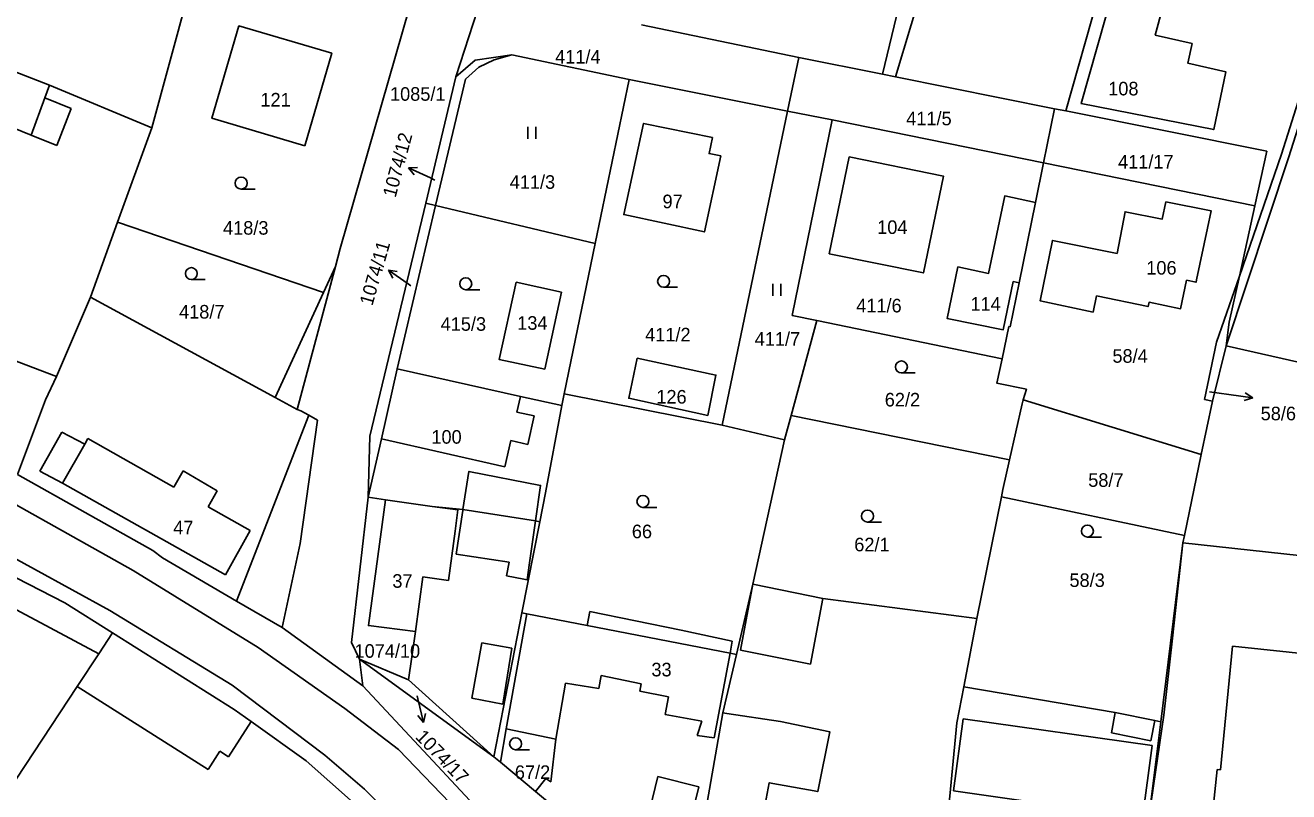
# Model space of a CAD drawing. Extents: x -746176 to -739709, y -1127410 to -1124482.
# Drawn here: x -742391.9 to -742233.7, y -1126006.4 to -1125910.5 of the extents above; entities that cross this region are included whole.
import ezdxf

# ---------------------------------------------------------------- set-up
doc = ezdxf.new("R2010")
doc.units = 0
for name, color, linetype in [('Hranice parcel', 7, 'Continuous'), ('Parcelní čísla', 7, 'Continuous'), ('Pop  PČ popisy', 7, 'Continuous'), ('Vnitřní kresba', 7, 'Continuous'), ('Značky kultur', 7, 'Continuous')]:
    doc.layers.add(name, color=color, linetype=linetype)

msp = doc.modelspace()

# ---------------------------------------------------------------- linework, layer by layer
at = {"layer": 'Hranice parcel'}
for p, q in [((-742261.6, -1125921.22), (-742251.35, -1125885.17)), ((-742284.56, -1125916.62), (-742279.49, -1125895.76)), ((-742369.56, -1125899.45), (-742376.04, -1125923.32)), ((-742337.98, -1125916.93), (-742332.93, -1125901.45)), ((-742314.74, -1125910.42), (-742295.02, -1125914.52)), ((-742316.28, -1125917.27), (-742330.95, -1125914.18)), ((-742296.43, -1125921.26), (-742295.02, -1125914.52)), ((-742295.02, -1125914.52), (-742284.56, -1125916.62)), ((-742341.73, -1125932.77), (-742337.98, -1125916.93)), ((-742316.28, -1125917.27), (-742320.52, -1125937.81)), ((-742296.43, -1125921.26), (-742316.28, -1125917.27)), ((-742282.91, -1125916.95), (-742284.56, -1125916.62)), ((-742282.91, -1125916.95), (-742263.01, -1125920.94)), ((-742264.39, -1125927.72), (-742263.01, -1125920.94)), ((-742263.01, -1125920.94), (-742261.6, -1125921.22)), ((-742304.63, -1125960.54), (-742296.43, -1125921.26)), ((-742296.43, -1125921.26), (-742290.84, -1125922.32)), ((-742290.84, -1125922.32), (-742264.39, -1125927.72)), ((-742380.33, -1125935.12), (-742376.04, -1125923.32)), ((-742264.39, -1125927.72), (-742265.4, -1125932.68)), ((-742237.93, -1125933.1), (-742264.39, -1125927.72)), ((-742340.51, -1125933.06), (-742345.34, -1125953.5)), ((-742340.51, -1125933.06), (-742341.73, -1125932.77)), ((-742340.51, -1125933.06), (-742320.52, -1125937.81)), ((-742267.46, -1125942.71), (-742265.4, -1125932.68)), ((-742239.87, -1125941.89), (-742237.93, -1125933.1)), ((-742380.33, -1125935.12), (-742383.73, -1125944.51)), ((-742354.55, -1125943.93), (-742380.33, -1125935.12)), ((-742320.52, -1125937.81), (-742324.4, -1125956.6)), ((-742353.05, -1125940.67), (-742354.55, -1125943.93)), ((-742383.73, -1125944.51), (-742387.99, -1125954.45)), ((-742360.59, -1125957.08), (-742383.73, -1125944.51)), ((-742360.59, -1125957.08), (-742354.55, -1125943.93)), ((-742292.77, -1125947.44), (-742295.99, -1125959.35)), ((-742269.58, -1125952.24), (-742292.77, -1125947.44)), ((-742241.51, -1125950.63), (-742243.24, -1125957.53)), ((-742215.07, -1125956.62), (-742241.51, -1125950.63)), ((-742324.4, -1125956.6), (-742324.69, -1125958.1)), ((-742304.63, -1125960.54), (-742324.4, -1125956.6)), ((-742266.93, -1125957.38), (-742244.64, -1125964.23)), ((-742243.24, -1125957.53), (-742244.64, -1125964.23)), ((-742243.24, -1125957.53), (-742244.22, -1125957.34)), ((-742296.81, -1125962.38), (-742304.63, -1125960.54)), ((-742295.99, -1125959.35), (-742296.81, -1125962.38)), ((-742268.65, -1125964.88), (-742295.99, -1125959.35)), ((-742296.81, -1125962.38), (-742300.78, -1125980.44)), ((-742244.64, -1125964.23), (-742246.75, -1125974.33)), ((-742348.95, -1125969.57), (-742346.78, -1125969.9)), ((-742269.67, -1125969.51), (-742272.76, -1125984.75)), ((-742246.75, -1125974.33), (-742269.67, -1125969.51)), ((-742329.7, -1125984.02), (-742327.47, -1125972.62)), ((-742246.75, -1125974.33), (-742246.94, -1125975.25)), ((-742246.94, -1125975.25), (-742249.72, -1125997.65)), ((-742246.94, -1125975.25), (-742222.55, -1125977.95)), ((-742300.78, -1125980.44), (-742302.83, -1125989.25)), ((-742329.7, -1125984.02), (-742333.21, -1126002.03)), ((-742274.38, -1125993.3), (-742272.76, -1125984.75)), ((-742380.97, -1125986.53), (-742382.69, -1125989.14)), ((-742350.03, -1125989.81), (-742343.92, -1125992.41)), ((-742333.21, -1126002.03), (-742350.03, -1125989.81)), ((-742350.03, -1125989.81), (-742349.63, -1125993.16)), ((-742343.92, -1125992.41), (-742333.21, -1126002.03)), ((-742275.24, -1125997.79), (-742274.38, -1125993.3)), ((-742276.95, -1126015.87), (-742275.24, -1125997.79)), ((-742249.72, -1125997.65), (-742254.82, -1126038.74)), ((-742332.39, -1126002.71), (-742333.21, -1126002.03)), ((-742327.99, -1126006.38), (-742332.39, -1126002.71))]:
    msp.add_line(p, q, dxfattribs=at)
for points in [[(-742241.51, -1125950.63), (-742233.66, -1125926.96), (-742223.23, -1125894.07), (-742218.91, -1125880.44), (-742217.69, -1125875.07), (-742216.33, -1125869.06)], [(-742239.87, -1125941.89), (-742234.61, -1125926.63), (-742224.19, -1125893.77)], [(-742279.49, -1125895.76), (-742277.04, -1125897.38), (-742282.91, -1125916.95)], [(-742252.47, -1125894.85), (-742259.69, -1125920.29), (-742243.08, -1125923.55), (-742241.58, -1125916.3), (-742246.33, -1125915.23), (-742245.79, -1125912.79), (-742250.41, -1125911.75), (-742246.32, -1125896.62), (-742252.47, -1125894.85)], [(-742343.77, -1125908.28), (-742352.46, -1125938.44), (-742353.05, -1125940.67)], [(-742356.87, -1125925.57), (-742368.52, -1125922.14), (-742365.15, -1125910.57), (-742353.51, -1125913.99), (-742356.87, -1125925.57)], [(-742376.04, -1125923.32), (-742388.87, -1125917.99), (-742404.91, -1125911.78)], [(-742330.95, -1125914.18), (-742333.17, -1125914.81), (-742335.12, -1125915.74), (-742336.77, -1125917.22), (-742340.51, -1125933.06)], [(-742337.98, -1125916.93), (-742335.56, -1125914.84), (-742330.95, -1125914.18)], [(-742261.6, -1125921.22), (-742236.44, -1125926.26), (-742237.93, -1125933.1)], [(-742305.85, -1125924.52), (-742314.47, -1125922.77), (-742316.95, -1125934.19), (-742306.85, -1125936.36), (-742304.8, -1125926.85), (-742306.27, -1125926.55), (-742305.85, -1125924.52)], [(-742290.84, -1125922.32), (-742295.85, -1125946.81), (-742292.77, -1125947.44)], [(-742288.73, -1125926.94), (-742291.23, -1125939.08), (-742279.43, -1125941.49), (-742276.92, -1125929.36), (-742288.73, -1125926.94)], [(-742265.4, -1125932.68), (-742269.24, -1125931.85), (-742271.28, -1125941.54), (-742275.1, -1125940.73), (-742276.46, -1125947.18), (-742269.43, -1125948.6), (-742268.18, -1125942.58), (-742267.46, -1125942.71)], [(-742348.95, -1125969.57), (-742348.77, -1125961.93), (-742341.73, -1125932.77)], [(-742249.09, -1125932.57), (-742249.52, -1125934.75), (-742254.17, -1125933.84), (-742255.18, -1125939.05), (-742263.28, -1125937.42), (-742264.8, -1125945), (-742258.18, -1125946.38), (-742257.75, -1125944.36), (-742251.29, -1125945.7), (-742251.18, -1125945.16), (-742247.23, -1125945.98), (-742246.48, -1125942.4), (-742245.29, -1125942.65), (-742245.23, -1125942.35), (-742243.85, -1125935.89), (-742243.41, -1125933.71), (-742249.09, -1125932.57)], [(-742324.73, -1125943.91), (-742326.85, -1125953.53), (-742332.56, -1125952.31), (-742330.42, -1125942.66), (-742324.73, -1125943.91)], [(-742267.46, -1125942.71), (-742268.58, -1125948.23), (-742268.73, -1125948.2), (-742269.58, -1125952.24)], [(-742244.22, -1125957.34), (-742242.72, -1125950.14), (-742239.87, -1125941.89)], [(-742241.51, -1125950.63), (-742241.14, -1125947.64), (-742239.87, -1125941.89)], [(-742417.31, -1125943.6), (-742412.38, -1125945.19), (-742387.99, -1125954.45)], [(-742315.28, -1125952.17), (-742305.42, -1125954.28), (-742306.43, -1125959.32), (-742316.33, -1125957.18), (-742315.28, -1125952.17)], [(-742269.58, -1125952.24), (-742270.22, -1125955.3), (-742266.54, -1125956.05), (-742266.93, -1125957.38)], [(-742444.75, -1125953.11), (-742386.93, -1125982.77), (-742380.97, -1125986.53)], [(-742387.99, -1125954.45), (-742389.36, -1125957.36), (-742392.86, -1125966.72)], [(-742345.34, -1125953.5), (-742347.31, -1125962.26), (-742348.95, -1125969.57)], [(-742324.69, -1125958.1), (-742329.9, -1125956.94), (-742345.34, -1125953.5)], [(-742382.69, -1125989.14), (-742398.6, -1125980.67), (-742445.94, -1125955.65)], [(-742357.41, -1125958.73), (-742357.86, -1125958.57), (-742360.59, -1125957.08)], [(-742268.65, -1125964.88), (-742267.07, -1125957.87), (-742266.93, -1125957.38)], [(-742365.43, -1125982.55), (-742356.37, -1125959.31), (-742357.41, -1125958.73)], [(-742327.47, -1125972.62), (-742326.77, -1125969.01), (-742324.69, -1125958.1)], [(-742269.67, -1125969.51), (-742269.48, -1125968.58), (-742268.65, -1125964.88)], [(-742392.86, -1125966.72), (-742375.94, -1125976.23), (-742374.7, -1125977.14), (-742365.43, -1125982.55)], [(-742327.47, -1125972.62), (-742328.01, -1125972.53), (-742327.37, -1125968.09), (-742336.35, -1125966.33), (-742337.09, -1125971.11), (-742340.95, -1125970.71), (-742346.78, -1125969.9)], [(-742350.03, -1125989.81), (-742351.04, -1125987.76), (-742348.95, -1125969.57)], [(-742346.78, -1125969.9), (-742348.93, -1125985.62), (-742343.03, -1125986.37), (-742343.92, -1125992.41)], [(-742272.76, -1125984.75), (-742292.04, -1125982.23), (-742300.78, -1125980.44)], [(-742365.43, -1125982.55), (-742359.74, -1125985.87), (-742349.63, -1125993.16)], [(-742302.83, -1125989.25), (-742303.65, -1125989.09), (-742321.55, -1125985.61), (-742329.11, -1125984.14), (-742329.7, -1125984.02)], [(-742380.97, -1125986.53), (-742365.73, -1125996.13), (-742363.63, -1125997.63), (-742356.74, -1126002.55), (-742344.5, -1126013.38)], [(-742382.69, -1125989.14), (-742385.4, -1125993.25), (-742394.08, -1126006.45)], [(-742302.83, -1125989.25), (-742304.53, -1125996.56), (-742309.51, -1126024.97)], [(-742349.63, -1125993.16), (-742329.2, -1126015.02), (-742324.67, -1126035.23)], [(-742249.72, -1125997.65), (-742250.44, -1125997.51), (-742255.43, -1125996.5), (-742274.38, -1125993.3)], [(-742332.39, -1126002.71), (-742331.66, -1125998.55), (-742325.47, -1125999.83), (-742326.09, -1126005.17), (-742326.73, -1126004.75), (-742327.99, -1126006.38)], [(-742309.51, -1126024.97), (-742309.85, -1126024.64), (-742311.67, -1126022.6), (-742317.81, -1126015.69), (-742320.62, -1126012.53), (-742327.99, -1126006.38)]]:
    msp.add_lwpolyline(points, dxfattribs=at)
at = {"layer": 'Pop  PČ popisy'}
for p, q in [((-742343.89, -1125928.332), (-742342.771, -1125928.301)), ((-742341.17, -1125929.6), (-742343.89, -1125928.332)), ((-742343.89, -1125928.332), (-742343.194, -1125929.209)), ((-742340.63, -1125929.86), (-742341.17, -1125929.6)), ((-742343.96, -1125942.86), (-742346.418, -1125941.139)), ((-742346.418, -1125941.139), (-742345.311, -1125941.303)), ((-742346.418, -1125941.139), (-742345.885, -1125942.123)), ((-742343.6, -1125943.11), (-742343.96, -1125942.86)), ((-742243.59, -1125956.38), (-742241.17, -1125956.7)), ((-742241.17, -1125956.7), (-742238.198, -1125957.118)), ((-742238.198, -1125957.118), (-742239.26, -1125957.474)), ((-742238.198, -1125957.118), (-742239.12, -1125956.482)), ((-742342.81, -1125994.4), (-742342.72, -1125994.81)), ((-742342.72, -1125994.81), (-742342.045, -1125997.734)), ((-742342.045, -1125997.734), (-742342.758, -1125996.871)), ((-742342.045, -1125997.734), (-742341.782, -1125996.646))]:
    msp.add_line(p, q, dxfattribs=at)
at = {"layer": 'Vnitřní kresba'}
for p, q in [((-742389.45, -1125919.59), (-742388.87, -1125917.99)), ((-742391.15, -1125924.26), (-742389.45, -1125919.59)), ((-742389.45, -1125919.59), (-742386.16, -1125920.91)), ((-742402.22, -1125919.77), (-742391.15, -1125924.26)), ((-742387.95, -1125925.55), (-742386.16, -1125920.91)), ((-742391.15, -1125924.26), (-742387.95, -1125925.55)), ((-742357.86, -1125958.57), (-742353.05, -1125940.67)), ((-742330.33, -1125958.91), (-742329.9, -1125956.94)), ((-742330.33, -1125958.91), (-742328.18, -1125959.38)), ((-742357.49, -1125975.36), (-742355.32, -1125959.9)), ((-742356.37, -1125959.31), (-742355.32, -1125959.9)), ((-742328.97, -1125962.95), (-742328.18, -1125959.38)), ((-742390.09, -1125966.29), (-742387.32, -1125961.4)), ((-742387.32, -1125961.4), (-742384.45, -1125962.91)), ((-742384.45, -1125962.91), (-742384.05, -1125962.22)), ((-742384.05, -1125962.22), (-742373.29, -1125968.32)), ((-742347.31, -1125962.26), (-742331.83, -1125965.77)), ((-742387.23, -1125967.82), (-742384.45, -1125962.91)), ((-742331.83, -1125965.77), (-742331.11, -1125962.48)), ((-742331.11, -1125962.48), (-742328.97, -1125962.95)), ((-742390.09, -1125966.29), (-742387.23, -1125967.82)), ((-742373.29, -1125968.32), (-742372.12, -1125966.26)), ((-742372.12, -1125966.26), (-742367.86, -1125968.77)), ((-742387.23, -1125967.82), (-742366.83, -1125979.29)), ((-742394.08, -1125969.92), (-742378.39, -1125978.73)), ((-742368.99, -1125970.76), (-742367.86, -1125968.77)), ((-742368.99, -1125970.76), (-742363.74, -1125973.74)), ((-742340.95, -1125970.71), (-742337.72, -1125971.14)), ((-742338.07, -1125973.8), (-742337.72, -1125971.14)), ((-742337.96, -1125976.7), (-742337.11, -1125971.22)), ((-742337.11, -1125971.22), (-742337.09, -1125971.11)), ((-742337.09, -1125971.11), (-742328.01, -1125972.53)), ((-742328.8, -1125978.06), (-742328.01, -1125972.53)), ((-742366.83, -1125979.29), (-742363.74, -1125973.74)), ((-742338.88, -1125979.98), (-742338.07, -1125973.8)), ((-742396.61, -1125975.35), (-742381.3, -1125983.74)), ((-742359.74, -1125985.87), (-742357.49, -1125975.36)), ((-742248.23, -1125987.21), (-742246.94, -1125975.25)), ((-742337.96, -1125976.7), (-742331.3, -1125977.68)), ((-742331.65, -1125979.39), (-742331.3, -1125977.68)), ((-742329.05, -1125979.9), (-742328.8, -1125978.06)), ((-742378.39, -1125978.73), (-742362.72, -1125988.35)), ((-742343.03, -1125986.37), (-742342.12, -1125979.52)), ((-742342.12, -1125979.52), (-742338.88, -1125979.98)), ((-742331.65, -1125979.39), (-742329.46, -1125979.82)), ((-742329.46, -1125979.82), (-742329.05, -1125979.9)), ((-742302.32, -1125988.68), (-742300.78, -1125980.44)), ((-742293.57, -1125990.45), (-742292.04, -1125982.23)), ((-742381.3, -1125983.74), (-742366, -1125993.07)), ((-742331.66, -1125998.55), (-742329.11, -1125984.14)), ((-742321.55, -1125985.61), (-742321.2, -1125983.86)), ((-742321.2, -1125983.86), (-742309.76, -1125986.21)), ((-742309.76, -1125986.21), (-742303.37, -1125987.59)), ((-742303.65, -1125989.09), (-742303.37, -1125987.59)), ((-742249.31, -1125996.84), (-742248.23, -1125987.21)), ((-742362.72, -1125988.35), (-742351.88, -1125995.99)), ((-742335.98, -1125994.7), (-742334.74, -1125987.77)), ((-742334.74, -1125987.77), (-742330.95, -1125988.45)), ((-742332.11, -1125995.44), (-742330.95, -1125988.45)), ((-742305.64, -1125999.67), (-742303.65, -1125989.09)), ((-742302.32, -1125988.68), (-742293.57, -1125990.45)), ((-742242.22, -1126003.67), (-742240.74, -1125988.18)), ((-742240.74, -1125988.18), (-742220, -1125990.44)), ((-742320.07, -1125993.48), (-742319.78, -1125991.88)), ((-742319.78, -1125991.88), (-742314.76, -1125992.93)), ((-742385.4, -1125993.25), (-742369.01, -1126003.63)), ((-742366, -1125993.07), (-742354.38, -1126001.86)), ((-742325.47, -1125999.83), (-742324.24, -1125992.82)), ((-742324.24, -1125992.82), (-742320.07, -1125993.48)), ((-742314.94, -1125993.84), (-742314.76, -1125992.93)), ((-742314.94, -1125993.84), (-742311.35, -1125994.55)), ((-742335.98, -1125994.7), (-742332.11, -1125995.44)), ((-742311.78, -1125996.77), (-742311.35, -1125994.55)), ((-742351.88, -1125995.99), (-742345.15, -1126001.12)), ((-742311.78, -1125996.77), (-742307.18, -1125997.57)), ((-742304.53, -1125996.56), (-742304.04, -1125996.64)), ((-742304.04, -1125996.64), (-742297.32, -1125997.63)), ((-742255.88, -1125999.05), (-742255.43, -1125996.5)), ((-742250.91, -1126007.68), (-742249.31, -1125996.84)), ((-742366.46, -1126002.04), (-742363.63, -1125997.63)), ((-742307.77, -1125999.4), (-742307.18, -1125997.57)), ((-742275.68, -1126006.29), (-742274.46, -1125997.29)), ((-742274.46, -1125997.29), (-742250.78, -1126000.65)), ((-742250.94, -1126000.04), (-742250.44, -1125997.51)), ((-742307.77, -1125999.4), (-742305.64, -1125999.67)), ((-742255.88, -1125999.05), (-742250.94, -1126000.04)), ((-742369.01, -1126003.63), (-742367.52, -1126001.35)), ((-742367.52, -1126001.35), (-742366.46, -1126002.04)), ((-742354.38, -1126001.86), (-742349.4, -1126006.1)), ((-742345.15, -1126001.12), (-742334.74, -1126011.95)), ((-742252.01, -1126009.69), (-742250.78, -1126000.65)), ((-742314.11, -1126010.3), (-742312.7, -1126004.51)), ((-742312.7, -1126004.51), (-742307.56, -1126005.82)), ((-742244, -1126016.27), (-742242.65, -1126003.62)), ((-742242.65, -1126003.62), (-742242.22, -1126003.67)), ((-742349.4, -1126006.1), (-742339.39, -1126016.09)), ((-742311.67, -1126022.6), (-742307.56, -1126005.82)), ((-742275.68, -1126006.29), (-742252.01, -1126009.69))]:
    msp.add_line(p, q, dxfattribs=at)
msp.add_lwpolyline([(-742297.32, -1125997.63), (-742291.14, -1125998.94), (-742292.67, -1126006.4), (-742298.74, -1126005.29), (-742299.24, -1126007.99)], dxfattribs=at)
at = {"layer": 'Značky kultur'}
for p, q in [((-742328.971, -1125924.71), (-742328.971, -1125923.21)), ((-742327.97, -1125924.71), (-742327.97, -1125923.21)), ((-742364.863, -1125931), (-742363.113, -1125931)), ((-742371.103, -1125942.32), (-742369.353, -1125942.32)), ((-742311.963, -1125943.29), (-742310.213, -1125943.29)), ((-742298.291, -1125944.34), (-742298.291, -1125942.84)), ((-742297.29, -1125944.34), (-742297.29, -1125942.84)), ((-742336.743, -1125943.59), (-742334.993, -1125943.59)), ((-742282.193, -1125954.01), (-742280.443, -1125954.01)), ((-742314.553, -1125970.83), (-742312.803, -1125970.83)), ((-742286.433, -1125972.66), (-742284.683, -1125972.66)), ((-742258.893, -1125974.54), (-742257.143, -1125974.54)), ((-742330.493, -1126001.16), (-742328.743, -1126001.16))]:
    msp.add_line(p, q, dxfattribs=at)
for centre in [(-742364.863, -1125930.25), (-742371.103, -1125941.57), (-742311.963, -1125942.54), (-742336.743, -1125942.84), (-742282.193, -1125953.26), (-742314.553, -1125970.08), (-742286.433, -1125971.91), (-742258.893, -1125973.79), (-742330.493, -1126000.41)]:
    msp.add_circle(centre, 0.75, dxfattribs=at)

# ---------------------------------------------------------------- texts
at = {"layer": 'Parcelní čísla'}
for s, p in [('411/4', (-742325.543, -1125915.28)), ('108', (-742256.29, -1125919.27)), ('121', (-742362.45, -1125920.66)), ('1085/1', (-742346.225, -1125919.94)), ('411/5', (-742281.583, -1125923.01)), ('411/17', (-742255.055, -1125928.43)), ('411/3', (-742331.233, -1125930.96)), ('97', (-742312.102, -1125933.39)), ('418/3', (-742367.133, -1125936.7)), ('104', (-742285.22, -1125936.61)), ('106', (-742251.52, -1125941.7)), ('411/6', (-742287.843, -1125946.43)), ('114', (-742273.54, -1125946.22)), ('418/7', (-742372.64, -1125947.2)), ('415/3', (-742339.883, -1125948.73)), ('134', (-742330.294, -1125948.6)), ('411/2', (-742314.273, -1125950.06)), ('411/7', (-742300.553, -1125950.59)), ('58/4', (-742255.761, -1125952.73)), ('126', (-742312.874, -1125957.84)), ('62/2', (-742284.27, -1125958.2)), ('58/6', (-742237.2, -1125959.933)), ('100', (-742341.044, -1125962.86)), ('58/7', (-742258.791, -1125968.26)), ('47', (-742373.372, -1125974.21)), ('66', (-742315.942, -1125974.69)), ('62/1', (-742288.09, -1125976.33)), ('37', (-742345.932, -1125980.89)), ('58/3', (-742261.141, -1125980.79)), ('1074/10', (-742350.668, -1125989.65)), ('33', (-742313.492, -1125991.98)), ('67/2', (-742330.591, -1126004.82))]:
    msp.add_text(s, height=1.7, dxfattribs=at).set_placement(p)
for s, rotation, p in [('1074/12', 75, (-742345.529, -1125932.147)), ('1074/11', 74, (-742348.438, -1125945.683)), ('1074/17', 314, (-742343.143, -1125999.648))]:
    msp.add_text(s, height=1.7, rotation=rotation, dxfattribs=at).set_placement(p)

doc.saveas('drawing.dxf')
